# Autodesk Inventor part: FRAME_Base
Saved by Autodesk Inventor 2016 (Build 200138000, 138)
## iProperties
Created: 2016-01
Part Number: FRAME_Base
Material: Generic
Document SubType Name: Modeling
Designer: John
Density: 1 g/cm^3
Appearance: Default
Author: John
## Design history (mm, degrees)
feature "SOLID1"
body "Solid1"
